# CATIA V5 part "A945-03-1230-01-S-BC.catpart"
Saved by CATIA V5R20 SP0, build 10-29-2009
Part number: A945-03-1230-01-S-BC
Source: Unknown
Property "ARTICLENO": "A945-03-1230-01-S-BC"
Property "B": "125.000"
Property "BOMINFO": "A945-03-1230-01-S-BC"
Property "CODE": "A945-03-1230-01-S-BC"
Property "D1": "26.000"
Property "D2": "17.500"
Property "D5": "20.000"
Property "D6": "16.000"
Property "H": "57.000"
Property "H1": "44.000"
Property "H2": "60.000"
Property "H3": "28.000"
Property "L1": "300.000"
Property "L2": "25.000"
Property "L3": "125.000"
Property "L4": "125.000"
Property "L5": "55.000"
Property "L6": "195.000"
Property "LINA": "A945-03-1230-01-S-BC"
Property "N": "8.000"
Property "NB": "A945-03-1230-01-S-BC"
Property "NBSYN": "$CODE."
Property "NN": "A945-03"
Property "NT": "v driver sets replaceable inserts pisitive return"
Property "SUPPLIER": "CF"
Property "Z": "85.000"
Bounding box of the stored display mesh (mm): x -669.473 to -511.473, y 748.188 to 833.188, z 0 to 300
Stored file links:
  C:\Users\Utente\Desktop\3D files A945-03\A945-03-1230-01-S-BC.catpart
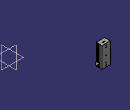
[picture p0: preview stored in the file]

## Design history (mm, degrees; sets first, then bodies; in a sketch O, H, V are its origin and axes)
Body1 "Geometry.1" (main body)
  Solid1 "A945-03-1230-01-S-BC.catpart": solid without history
